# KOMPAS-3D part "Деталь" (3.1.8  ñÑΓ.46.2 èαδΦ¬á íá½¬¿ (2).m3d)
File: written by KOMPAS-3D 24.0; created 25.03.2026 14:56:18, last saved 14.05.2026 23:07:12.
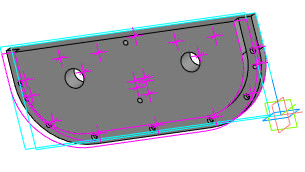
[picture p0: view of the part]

Document properties: Автор: TMK; Полное имя файла: E:\test_kompas\all_v22\3.1.8  дет.46.2 Крышка балки (2).m3d; Организация: TMK

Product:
- Part/product: Деталь
    Масса: 21.934157

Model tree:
1. Операция без истории:1
2. Эскиз:1
3. Смещенная плоскость:1  (with: Грань.Операция без истории:1)
4. Эскиз:2
5. Смещенная плоскость:2  (with: Грань.Операция без истории:1)
6. Эскиз:3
